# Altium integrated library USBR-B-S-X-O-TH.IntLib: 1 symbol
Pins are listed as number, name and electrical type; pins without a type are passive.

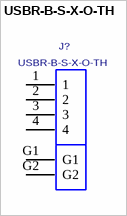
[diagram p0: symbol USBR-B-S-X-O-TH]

## USBR-B-S-X-O-TH
designator J?
HIGH RETENTION USB TYPE B CONNECTOR THRU HOLE; MANUFACTURER: SAMTEC
footprint USBR-B-S-X-O-TH
pins: 1, 2, 3, 4, G1, G2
